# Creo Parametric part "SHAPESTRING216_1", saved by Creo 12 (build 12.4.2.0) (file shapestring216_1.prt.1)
Units: Custom; MM, KILOGRAM, SECS

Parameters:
  PTC_WM_ITERATION = "0"
  PTC_WM_VERSION = "-.0"
  PTC_WM_LIFECYCLE_STATE = "In Work"
  PTC_WM_LIFECYCLE = "MO_CADDocument"
  PTC_WM_CREATED_BY = "Maximilian Roepper (Z0017RMS: MO)"
  PTC_WM_CREATED_ON = "18-Sep-26 11:36:42 AM"
  PTC_WM_MODIFIED_BY = "Maximilian Roepper (Z0017RMS: MO)"
  PTC_WM_MODIFIED_ON = "18-Sep-26 11:36:46 AM"
  PDMLINKNUMBER = "PDM000071455284"
  PTC_WM_NAME = "shapestring216_1.prt"
  PTC_WM_NUMBER = "PDM000071455284"

Other parameters: WEIGHT, WEIGHT_FACTOR, WEIGHT_ADD, _MASS_TEMP, _DIFF_TEMP, MC_ERRORS, SUPPLIER

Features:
  1. coordinate system
  2. datum plane "PRT_YZ"
  3. datum plane "PRT_XY"
  4. datum plane "PRT_XZ"
  5. coordinate system
  6. datum axis
  7. datum axis
  8. datum axis
  9. coordinate system
  10. imported feature

Other named items: PRT, SIEMENS_MO, DRW_VIEW_ORG, PRT_X, PRT_Y, PRT_Z, CS0, ROUGH_GROB

Layers: 00_STD_CSYS-KSYS, 01_STD_PLANES-EBENEN, 02_STD_AXES-ACHSEN, 03_STD_CSYS-KSYS, 24_IMPORT_FEAT-IMPORT_KE, INTFCLR

Surfaces: 1 plane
